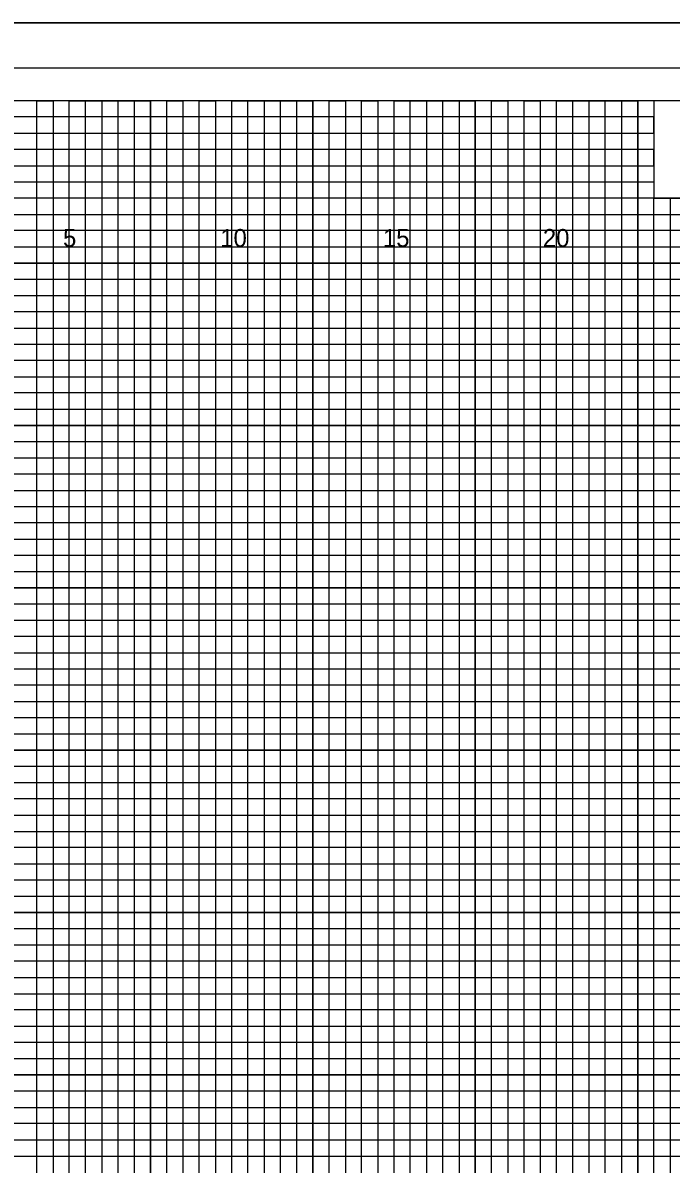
# Model space of a CAD drawing. Extents: x -4 to 103, y -2 to 138.
# Drawn here: x 54.82 to 74.78, y 103.08 to 138.22 of the extents above; entities that cross this region are included whole.
import ezdxf

# ---------------------------------------------------------------- set-up
doc = ezdxf.new("R2010")
doc.units = 0
for name, color, linetype in [('Old_Level_10', 7, 'Continuous'), ('Old_Level_3', 7, 'Continuous'), ('Old_Level_4', 7, 'Continuous'), ('Old_Level_5', 7, 'Continuous'), ('Old_Level_8', 7, 'Continuous'), ('Prop XS Elevation Labels', 7, 'Continuous'), ('Prop XS Finish Grade', 7, 'Continuous'), ('Prop XS Finish Grade Pavement', 7, 'Continuous')]:
    doc.layers.add(name, color=color, linetype=linetype)

msp = doc.modelspace()

# ---------------------------------------------------------------- linework, layer by layer
at = {"layer": 'Old_Level_10'}
for p, q in [((56.25, 70.825), (56.25, 135.825)), ((58.75, 70.825), (58.75, 135.825)), ((61.25, 70.825), (61.25, 135.825)), ((63.75, 70.825), (63.75, 135.825)), ((66.25, 70.825), (66.25, 135.825)), ((68.75, 70.825), (68.75, 135.825)), ((71.25, 70.825), (71.25, 135.825)), ((73.75, 70.825), (73.75, 135.825)), ((0, 133.325), (74.25, 133.325)), ((0, 130.825), (102.5, 130.825)), ((0, 128.325), (102.5, 128.325)), ((0, 125.825), (102.5, 125.825)), ((0, 123.325), (102.5, 123.325)), ((0, 120.825), (102.5, 120.825)), ((0, 118.325), (102.5, 118.325)), ((0, 115.825), (102.5, 115.825)), ((0, 113.325), (102.5, 113.325)), ((0, 110.825), (102.5, 110.825)), ((0, 108.325), (102.5, 108.325)), ((0, 105.825), (102.5, 105.825)), ((0, 103.325), (102.5, 103.325))]:
    msp.add_line(p, q, dxfattribs=at)
at = {"layer": 'Old_Level_3'}
msp.add_line((-3.5, 138.225), (103.4, 138.225), dxfattribs=at)
at = {"layer": 'Old_Level_4'}
msp.add_lwpolyline([(103, 136.825), (-2.8, 136.825), (-2.8, 69.825), (103, 69.825)], close=True, dxfattribs=at)
at = {"layer": 'Old_Level_5'}
msp.add_lwpolyline([(103.4, 138.225), (-3.5, 138.225), (-3.5, 68.4), (103.4, 68.4)], close=True, dxfattribs=at)
at = {"layer": 'Old_Level_8'}
for points in [[(56.25, 70.825), (56.25, 135.825), (58.75, 135.825), (58.75, 70.825)], [(61.25, 70.825), (61.25, 135.825), (63.75, 135.825), (63.75, 70.825)], [(66.25, 70.825), (66.25, 135.825), (68.75, 135.825), (68.75, 70.825)], [(71.25, 70.825), (71.25, 135.825), (73.75, 135.825), (73.75, 70.825)], [(0, 133.325), (74.25, 133.325)], [(0, 128.325), (102.5, 128.325), (102.5, 130.825), (0, 130.825)], [(0, 123.325), (102.5, 123.325), (102.5, 125.825), (0, 125.825)], [(0, 118.325), (102.5, 118.325), (102.5, 120.825), (0, 120.825)], [(0, 113.325), (102.5, 113.325), (102.5, 115.825), (0, 115.825)], [(0, 108.325), (102.5, 108.325), (102.5, 110.825), (0, 110.825)], [(0, 103.325), (102.5, 103.325), (102.5, 105.825), (0, 105.825)]]:
    msp.add_lwpolyline(points, dxfattribs=at)
at = {"layer": 'Prop XS Elevation Labels'}
for points in [[(102.5, 135.825), (0, 135.825), (0, 70.825), (102.5, 70.825)], [(83.75, 135.825), (74.25, 135.825), (74.25, 132.825), (83.75, 132.825)]]:
    msp.add_lwpolyline(points, close=True, dxfattribs=at)
at = {"layer": 'Prop XS Finish Grade'}
for points in [[(55.25, 70.825), (55.25, 135.825), (55.75, 135.825), (55.75, 70.825)], [(56.75, 70.825), (56.75, 135.825), (57.25, 135.825), (57.25, 70.825)], [(57.75, 70.825), (57.75, 135.825), (58.25, 135.825), (58.25, 70.825)], [(59.25, 70.825), (59.25, 135.825), (59.75, 135.825), (59.75, 70.825)], [(60.25, 70.825), (60.25, 135.825), (60.75, 135.825), (60.75, 70.825)], [(61.75, 70.825), (61.75, 135.825), (62.25, 135.825), (62.25, 70.825)], [(62.75, 70.825), (62.75, 135.825), (63.25, 135.825), (63.25, 70.825)], [(64.25, 70.825), (64.25, 135.825), (64.75, 135.825), (64.75, 70.825)], [(65.25, 70.825), (65.25, 135.825), (65.75, 135.825), (65.75, 70.825)], [(66.75, 70.825), (66.75, 135.825), (67.25, 135.825), (67.25, 70.825)], [(67.75, 70.825), (67.75, 135.825), (68.25, 135.825), (68.25, 70.825)], [(69.25, 70.825), (69.25, 135.825)], [(69.25, 135.825), (69.75, 135.825), (69.75, 70.825)], [(70.25, 70.825), (70.25, 135.825), (70.75, 135.825), (70.75, 70.825)], [(71.75, 70.825), (71.75, 135.825), (72.25, 135.825), (72.25, 70.825)], [(72.75, 70.825), (72.75, 135.825), (73.25, 135.825), (73.25, 70.825)], [(0, 132.825), (0, 133.825), (74.25, 133.825), (74.25, 134.325), (0, 134.325), (0, 134.825), (74.25, 134.825), (74.25, 135.325), (0, 135.325)], [(0, 132.325), (102.5, 132.325), (102.5, 132.825), (0, 132.825)], [(74.25, 70.825), (74.25, 132.825), (74.75, 132.825), (74.75, 70.825)], [(0, 131.325), (102.5, 131.325), (102.5, 131.825), (0, 131.825)], [(0, 129.825), (102.5, 129.825), (102.5, 130.325), (0, 130.325)], [(0, 128.825), (102.5, 128.825), (102.5, 129.325), (0, 129.325)], [(0, 127.325), (102.5, 127.325), (102.5, 127.825), (0, 127.825)], [(0, 126.325), (102.5, 126.325), (102.5, 126.825), (0, 126.825)], [(0, 124.825), (102.5, 124.825), (102.5, 125.325), (0, 125.325)], [(0, 123.825), (102.5, 123.825), (102.5, 124.325), (0, 124.325)], [(0, 122.325), (102.5, 122.325), (102.5, 122.825), (0, 122.825)], [(0, 121.325), (102.5, 121.325), (102.5, 121.825), (0, 121.825)], [(0, 119.825), (102.5, 119.825), (102.5, 120.325), (0, 120.325)], [(0, 118.825), (102.5, 118.825), (102.5, 119.325), (0, 119.325)], [(0, 117.325), (102.5, 117.325), (102.5, 117.825), (0, 117.825)], [(0, 116.325), (102.5, 116.325), (102.5, 116.825), (0, 116.825)], [(0, 114.825), (102.5, 114.825), (102.5, 115.325), (0, 115.325)], [(0, 113.825), (102.5, 113.825), (102.5, 114.325), (0, 114.325)], [(0, 112.325), (102.5, 112.325), (102.5, 112.825), (0, 112.825)], [(0, 111.325), (102.5, 111.325), (102.5, 111.825), (0, 111.825)], [(0, 109.825), (102.5, 109.825), (102.5, 110.325), (0, 110.325)], [(0, 108.825), (102.5, 108.825), (102.5, 109.325), (0, 109.325)], [(0, 107.325), (102.5, 107.325), (102.5, 107.825), (0, 107.825)], [(0, 106.325), (102.5, 106.325), (102.5, 106.825), (0, 106.825)], [(0, 104.825), (102.5, 104.825), (102.5, 105.325), (0, 105.325)], [(0, 103.825), (102.5, 103.825), (102.5, 104.325), (0, 104.325)]]:
    msp.add_lwpolyline(points, dxfattribs=at)

# ---------------------------------------------------------------- texts
at = {"layer": 'Prop XS Finish Grade Pavement'}
for s, p in [('5', (56.057, 131.325)), ('10', (60.897, 131.325)), ('15', (65.906, 131.325)), ('20', (70.831, 131.325))]:
    msp.add_text(s, height=0.55, dxfattribs=at).set_placement(p)

doc.saveas('drawing.dxf')
